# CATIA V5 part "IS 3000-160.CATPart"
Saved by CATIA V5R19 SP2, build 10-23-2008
Part number: IS 3000-160
Bounding box of the stored display mesh (mm): x -47.487 to 47.487, y -47.487 to 47.487, z 0 to 440
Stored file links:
  C:\Users\Bora\Desktop\3D Katı model\IS serisi\IS 3000\IS 3000-160.CATPart
  C:\Program Files\Dassault Systemes\B19\intel_a\reffiles\standard\MetricThickPitch.txt
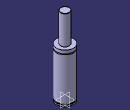
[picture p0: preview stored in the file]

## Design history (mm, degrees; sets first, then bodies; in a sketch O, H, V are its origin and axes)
Body1 (main body)
  Sketch1 on yz-plane, origin (0, 0, 0), H (0, 1, 0), V (0, 0, 1)
    point P1 (47.5, 258.5)
    point P4 (47.5, 253.5)
    point P7 (25, 439)
    point P9 (25, 439)
    point P13 (47.5, 258.5)
    point P14 (47.5, 253.5)
    line L1 (47.5, 258.5) -> (47.5, 277)
    line L2 (47.5, 13) -> (47.5, 253.5)
    line L3 (43.5, 13) -> (43.5, 8)
    arc A1 centre (24, 439) radius 1 from (25, 439) to (24, 440) ccw
    line L4 (25, 439) -> (25, 277)
    line L5 (47.5, 0) -> (47.5, 8)
    arc A2 centre (47.5, 256) radius 2.5 from (47.5, 258.5) to (47.5, 253.5) ccw
    line L6 (24, 440) -> (0, 440)
    point P15 (0, 440)
    line L7 (25, 277) -> (47.5, 277)
    line L8 (0, 0) -> (47.5, 0)
    line L9 (43.5, 8) -> (47.5, 8)
    line L10 (43.5, 13) -> (47.5, 13)
    coincidence: P15 V, P1 P13, P4 P14, P7 P9
    tangency: L6 A1
    horizontal: L7 H, L8 H, L9 H, L10 H
  Shaft1: profile Sketch1, axis Sketch1.V, angle 360
  Sketch2 on face of Shaft1 from Sketch1.L8, origin (0, 0, 0), H (1, 0, 0), V (0, -1, 0)
    point P1 (30, 0)
    distance P1 V = 30
  Hole1: placed by Sketch2, at (30, 0, 0) direction (0, 0, 1), diameter 6.647, depth 13, threaded "M8", thread diameter 8, thread depth 13, pitch 1.25
  CircPattern1: of Hole1, instances 4, angular step 90, axis from xy-plane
